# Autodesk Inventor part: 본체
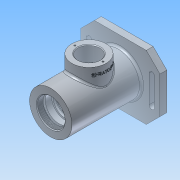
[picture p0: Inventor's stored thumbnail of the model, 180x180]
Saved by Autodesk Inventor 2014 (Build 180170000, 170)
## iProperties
Created: 2017-10
Part Number: 본체
Material: 알루미늄 6061
Document SubType Name: Modeling
Designer: NET
Density: 2.71 g/cm^3
Appearance: 알루미늄 - 평지
Mass: 740.697 g
Surface Area: 652.829 cm^2
Volume: 273.32 cm^3
Author: NET
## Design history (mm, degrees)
sketch "스케치1"
  geometry: L1 (-58, 47)-(58, 47); L2 (58, 47)-(58, -47); L3 (58, -47)-(-58, -47); L4 (-58, -47)-(-58, 47); L5 (-58, 47)-(58, -47); L6 (58, 47)-(-58, -47); 3 further points
  constraints: 12 end point, 3 midpoint, 2 parallel, 1 coincident, 1 horizontal, 1 perpendicular
  dimensions: "d0" = 116 distance of L1.start L1.end; "d1" = 94 distance of L1.end L2.end
extrude "돌출1" new body sketch "스케치1" distance "d2" = 10; taper "d3" = 0 deg
sketch "스케치2"
  geometry: C1 r 31 at (0, 0); 1 further point
  constraints: 1 centre point, 1 coincident
  dimensions: "d4" = 62 diameter of C1
extrude "돌출2" join sketch "스케치2" distance "d5" = 102; taper "d6" = 0 deg
sketch "스케치3"
  geometry: C1 r 35 at (0, 0); 1 further point
  constraints: 1 centre point, 1 coincident
  dimensions: "d7" = 70 diameter of C1
extrude "돌출3" join sketch "스케치3" distance "d8" = 3; taper "d9" = 0 deg
sketch "스케치4"
  geometry: L1 (-35, -3)-(35, -3) reference; L2 (31, 112)-(-31, 112) reference; L3 (0, 112)-(0, -3); L4 (0, 112)-(21, 112); L5 (21, 112)-(21, 103); L6 (0, 103)-(24, 103); L7 (24, 103)-(24, 100); L8 (24, 100)-(20, 100); L9 (20, 100)-(20, 91); L10 (20, 91)-(17.5, 91); L11 (17.5, 91)-(17.5, 87.75); L12 (17.5, 87.75)-(18.5, 87.75); L13 (18.5, 87.75)-(18.5, 86); L14 (18.5, 86)-(17.5, 86); L15 (17.5, 86)-(17.5, 75); L16 (17.5, 75)-(26, 75); L17 (26, 75)-(26, 37); L18 (26, 37)-(17.5, 37); L19 (17.5, 37)-(17.5, 26); L20 (17.5, 26)-(16.5, 26); L21 (16.5, 26)-(16.5, 21); L22 (16.5, 21)-(10, 21); L23 (10, 21)-(10, 18.3); L24 (10, 18.3)-(12.5, 18.3); L25 (12.5, 18.3)-(12.5, 11); L26 (0, -3)-(22, -3); L27 (12.5, 11)-(16, 11); L28 (16, 11)-(22, -3); 2 further points
  constraints: 52 end point, 18 parallel, 5 point on line, 4 perpendicular, 3 collinear, 2 midpoint
  dimensions: "d40" = 42 diameter of L5 L3; "d41" = 48 diameter of L7 L3; "d42" = 40 diameter of L9 L3; "d43" = 35 diameter of L11 L3; "d44" = 37 diameter of L13 L3; "d45" = 52 diameter of L17 L3; "d46" = 33 diameter of L21 L3; "d47" = 20 diameter of L23 L3; "d48" = 25 diameter of L25 L3; "d50" = 7.3 distance of L24.end L25.end; "d51" = 2.7 distance of L22.end L23.end; "d52" = 5 distance of L20.end L21.end; "d53" = 11 distance of L18.end L19.end; "d54" = 38 distance of L16.end L17.end; "d55" = 1.75 distance of L12.end L13.end; "d56" = 3.25 distance of L10.end L11.end; "d57" = 9 distance of L8.end L9.end; "d58" = 3 distance of L6.end L7.end; "d62" = 44 diameter of L26.end L3; "d63" = 32 diameter of L27.end L3; "d64" = 14 distance between parallel lines of L1 L27
hole "구멍1" diameter "d12" = 40.376; stored, may be unused: countersink angle "d16" = 90 deg, drill point angle "d18" = 0 deg; dims "d13" = 6, "d14" = 4, "d15" = 2, "d17" = 9, "d60" = 10, "d61" = 10
revolve "회전1" stored, may be unused: angle "d59" = 90 deg
node "작업 평면1"
sketch "스케치5"
  geometry: L1 (31, 112)-(-31, 112) reference; C1 r 25 at (0, 56); 2 further points
  constraints: 1 centre point, 1 midpoint, 1 vertical alignment
  dimensions: "d66" = 56 distance from line of L1 C1.centre; "d67" = 50 diameter of C1
extrude "돌출4" join sketch "스케치5" stored distance "d68" = 9; taper "d69" = 0 deg
hole "구멍2" diameter "d72" = 32; stored, may be unused: countersink angle "d76" = 90 deg, drill point angle "d78" = 0 deg; dims "d70" = 10, "d71" = 10, "d73" = 6, "d74" = 4, "d75" = 2, "d77" = 47
chamfer "모따기1" distance "d79" = 20; stored, may be unused: second distance "d80" = 2, angle "d81" = 45 deg
sketch "스케치6"
  geometry: L1 (58, -27)-(58, 27) reference; L2 (-38, -47)-(38, -47) reference; L3 (46, 20)-(46, -20); L4 (42, 20)-(42, -20); L5 (50, -20)-(50, 20); C1 r 35 at (0, 0) reference; A1 r 4 centre (46, 20) between (50, 20) and (42, 20); A2 r 4 centre (46, -20) between (42, -20) and (50, -20); 3 further points
  constraints: 8 end point, 4 point on circle, 4 tangent, 3 midpoint, 2 centre point, 1 horizontal alignment, 1 parallel, 1 perpendicular
  dimensions: "d82" = 4 radius of A1; "d83" = 46 horizontal distance of L3.end C1.centre; "d84" = 40 distance of L5.start L5.end
extrude "돌출5" cut sketch "스케치6" stored distance "d85" = 9; taper "d86" = 0 deg
sketch "스케치7"
  geometry: C1 r 16 at (0, 0) reference; 3 further points
  constraints: 2 horizontal alignment
  dimensions: "d87" = 20.5 distance of C1.centre point (-20.5, 0); "d88" = 20.5 distance of C1.centre point (20.5, 0)
hole "구멍3" sketch "스케치7" at (-20.5, 0), (20.5, 0) diameter "d89" = 2.459; stored, may be unused: countersink angle "d93" = 90 deg, drill point angle "d95" = 118 deg; dims "d90" = 6, "d91" = 4, "d92" = 2, "d94" = 8
node "작업 평면2"
sketch "스케치8"
  geometry: L1 (0, 25)-(0, -25) reference; L2 (-16, 56)-(-78, 56) reference; 2 further points
  constraints: 1 other
  dimensions: "d96" = 10 distance from line of L1 point (-10, 0); "d97" = 56 distance from line of L2 point (-10, 0)
feature "엠보싱1" sketch "스케치8" dims "d0" = 116, "d1" = 94, "d98" = 0.5, "d99" = 0
chamfer "모따기2" distance "d100" = 1; stored, may be unused: second distance "d101" = 2, angle "d102" = 45 deg
chamfer "모따기3" distance "d103" = 1; stored, may be unused: second distance "d104" = 2, angle "d105" = 45 deg
chamfer "모따기4" distance "d106" = 0.7; stored, may be unused: second distance "d107" = 2, angle "d108" = 30 deg
chamfer "모따기5" distance "d109" = 1; stored, may be unused: second distance "d110" = 2, angle "d111" = 45 deg
chamfer "모따기6" distance "d112" = 1; stored, may be unused: second distance "d113" = 2, angle "d114" = 45 deg
fillet "모깎기1" dims "d115" = 0.3
fillet "모깎기2" dims "d116" = 3
fillet "모깎기3" dims "d117" = 3
fillet "모깎기4" dims "d118" = 3
node "솔리드1"
mirror "대칭1"
other parameters: "d65" = 47
